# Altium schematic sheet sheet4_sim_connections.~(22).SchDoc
size A3; Author: Mauri Shadi; CompanyName: BFH; DrawnBy: Mauri Shadi; SheetNumber: 1; SheetTotal: 3
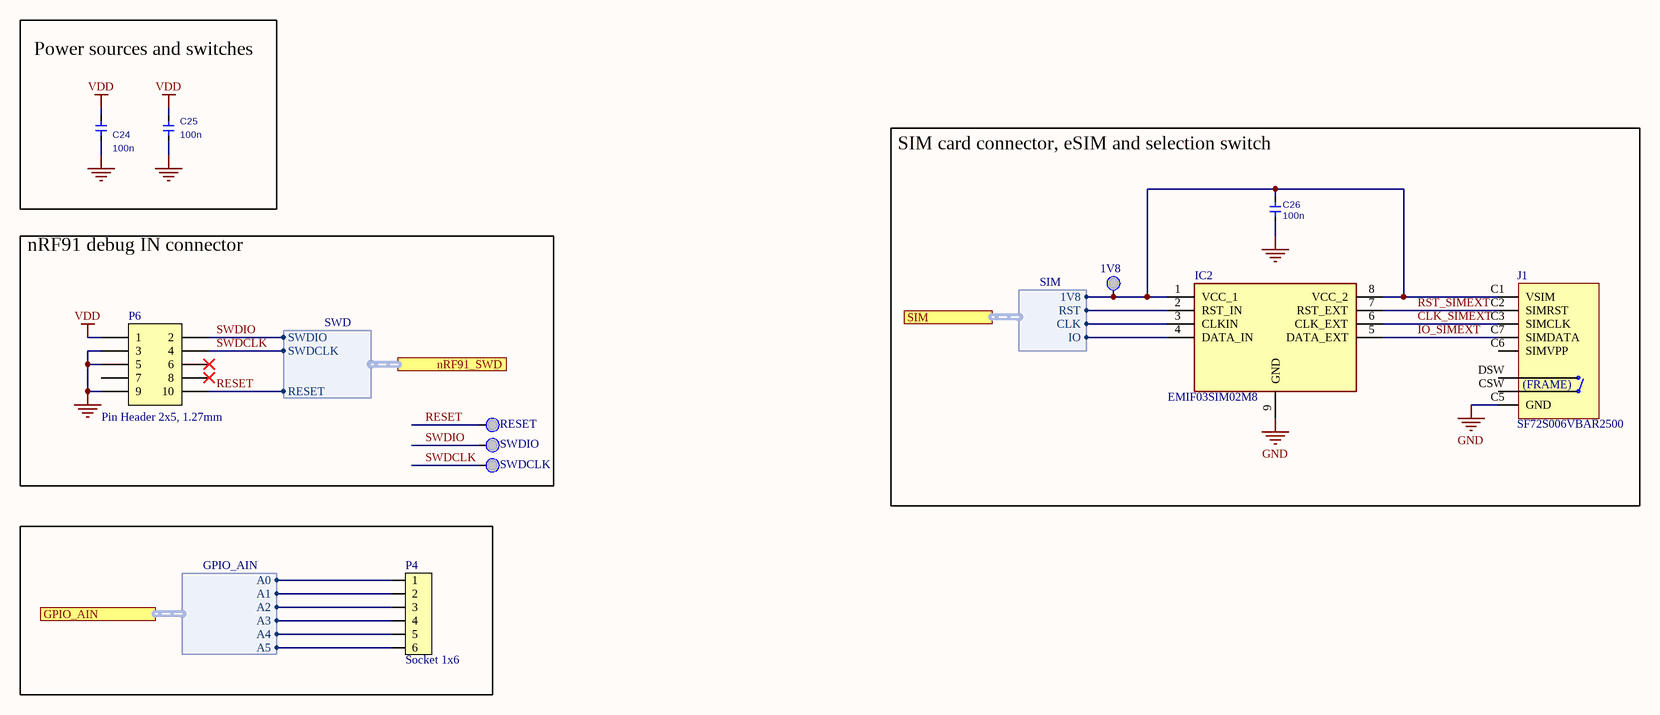
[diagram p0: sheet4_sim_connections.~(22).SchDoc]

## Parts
1V8  TESTPOINT_Black_Small  [Testpoint_Black_Small]  (value not drawn)
C24  100n  [0603(1608)C]
C25  100n  [0603(1608)C]
C26  100n  [0603(1608)C]
IC2  EMIF03SIM02M8  [SON40P150X170X60-9N-D]
J1  SF72S006VBAR2500  [SF72S006VBAR2500]
P4  Socket 1x6  [SOCKET_1x6_SMD]
P6  Pin Header 2x5, 1.27mm  [HDR_2x5-SMD-1.27mm-K]
RESET  TESTPOINT_Black_Small  [Testpoint_Black_Small]  (value not drawn)
SWDCLK  TESTPOINT_Black_Small  [Testpoint_Black_Small]  (value not drawn)
SWDIO  TESTPOINT_Black_Small  [Testpoint_Black_Small]  (value not drawn)

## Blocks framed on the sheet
Power sources and switches: C24 C25
SIM card connector, eSIM and selection switch: 1V8 C26 IC2 J1
nRF91 debug IN connector: P6 RESET SWDCLK SWDIO

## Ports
GPIO_AIN (harness GPIO_AIN, see sheet2_nRF9160[7C]), nRF91_SWD (harness SWD, see sheet2_nRF9160[7D]), SIM (harness SIM, see sheet2_nRF9160[7C])

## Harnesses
SWD: SWDIO, SWDCLK, RESET
GPIO_AIN: A0, A1, A2, A3, A4, A5
SIM: CLK, IO, 1V8, RST

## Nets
GND: C24.2 C25.1 C26.1 IC2.9(GND) J1.0(GND) J1.C5(GND) P6.3 P6.5 P6.9
VDD: C24.1 C25.2 P6.1
CLK_SIMEXT: IC2.6(CLK_EXT) J1.C3(SIMCLK)
IO_SIMEXT: IC2.5(DATA_EXT) J1.C7(SIMDATA)
RESET: P6.10 RESET.1 ; port nRF91_SWD.RESET
RST_SIMEXT: IC2.7(RST_EXT) J1.C2(SIMRST)
SWDCLK: P6.4 SWDCLK.1 ; port nRF91_SWD.SWDCLK
SWDIO: P6.2 SWDIO.1 ; port nRF91_SWD.SWDIO
Net1V8_1: 1V8.1 C26.2 IC2.1(VCC_1) IC2.8(VCC_2) J1.C1(VSIM) ; port SIM.1V8
NetIC2_2: IC2.2(RST_IN) ; port SIM.RST
NetIC2_3: IC2.3(CLKIN) ; port SIM.CLK
NetIC2_4: IC2.4(DATA_IN) ; port SIM.IO
NetP4_1: P4.1 ; port GPIO_AIN.A0
NetP4_2: P4.2 ; port GPIO_AIN.A1
NetP4_3: P4.3 ; port GPIO_AIN.A2
NetP4_4: P4.4 ; port GPIO_AIN.A3
NetP4_5: P4.5 ; port GPIO_AIN.A4
NetP4_6: P4.6 ; port GPIO_AIN.A5

Not connected (* = marked no-connect by the designer): J1 C6(SIMVPP) CSW DSW; P6 6* 7 8*

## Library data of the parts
1V8 RESET SWDCLK SWDIO = TESTPOINT_Black_Small: PCB Test Point, Black, Through Hole Mount, 3.2 mm, Phosphor Bronze; Manufacturer: MULTICOMP; Manufacturer P/N: TEST-1(R)
C24 C25 = C0603_5_100n_25V: Cer Chip Capacitor / 100n/ +-5%/ 25V; Manufacturer Part Number: CC0603KRX7R8BB104; Manufacturer 1: Yageo; Special Value 1: +-5%; Capacitance: 100nF; Tolerance: 10%; Dielectric: X7R
C26 = C0603_5_100n_25V: Cer Chip Capacitor / 100n/ +-5%/ 25V; Manufacturer 1: Yageo; Manufacturer Part Number: CC0603KRX7R8BB104; Special Value 1: +-5%; Capacitance: 100nF; Tolerance: 10%; Dielectric: X7R
IC2 = EMIF03SIM02M8: Integrated Circuit; Manufacturer_Name: STMicroelectronics
J1 = SF72S006VBAR2500: n 8 (6 + 2) Position Card Connector NANO SIM Surface Mount, Right Angle Gold; Manufacturer: JAE Electronics; Part number IPS: 00000009956; Note: N.A.; Pad Count: 8
P4 = Socket 1x6 SMD: Socket 1x6, 2.54mm (100mil), SMD; Manufacturer: W-CON; Manufacturer Part Number: 2171-106MS0CUNR1; Part number IPS: 00000009964; Note: N.A.; Artikkelnr Noca: 55030001; Pad Count: 6
P6 = Pin Header 2x5 SMD, 1.27mm, KS: Pin Header 2x5, 1.27mm (50mil), SMD, Keying Shroud; Manufacturer: W-CON; Manufacturer Part Number: 3132-10MS0BK00R1; Part number IPS: 00000009968; Note: N.A.; Artikkelnr Noca: 55010009; Pad Count: 10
